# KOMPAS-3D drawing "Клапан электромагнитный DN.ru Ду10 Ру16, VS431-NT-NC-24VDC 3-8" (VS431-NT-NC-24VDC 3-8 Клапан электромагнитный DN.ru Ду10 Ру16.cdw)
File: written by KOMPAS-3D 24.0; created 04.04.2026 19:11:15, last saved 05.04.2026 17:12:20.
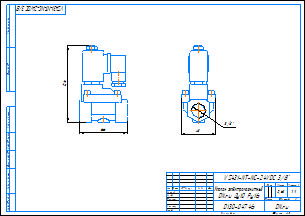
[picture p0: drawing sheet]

Document properties: c3d_UniqueCompID: ef56311e-7521-43dc-8291-0e6108b3d81d; Обозначение: VS400-ET-NC-220VAC 3-8; Наименование: Клапан электромагнитный DN.ru Ду10 Ру16; Автор: artio; Класс точности: c; Знак неуказанной шероховатости: Шероховатость не задана; Рассекать на разрезах: Да; Автор: artio; Форматы листов документа: A3; Полное имя файла: VS431-NT-NC-24VDC 3-8 Клапан электромагнитный DN.ru Ду10 Ру16.m3d; Масса: 0.62; Наименование: Клапан электромагнитный DN.ru Ду10 Ру16; Количество листов документа: 1; Примечание: D130-04746

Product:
- Body: Тело 1  | qty 1
    Масса: 1.030062
- Part/product: Клапан электромагнитный DN.ru Ду10 Ру16  | designation VS431-NT-NC-24VDC 3-8
    Масса: 0.62
    Раздел спецификации: Прочие изделия
    Примечание: D130-04746
    additional columns: ef56311e-7521-43dc-8291-0e6108b3d81d; VS400-ET-NC-220VAC 3-8; artio; c; Шероховатость не задана; Да

Views: Вид 1, Спереди, Проекционный вид 2
Referenced files in C:\Users\artio\OneDrive\Рабочий стол\Клапан электромагнитный DN.ru\VS400-ET-NC\VS400-ET-NC-24VDC\: VS400-ET-NC-24VDC 3-8 Клапан электромагнитный DN.ru Ду10 Ру16.m3d
Referenced files in C:\Users\artio\OneDrive\Рабочий стол\Клапан электромагнитный DN.ru\VS431\VS431-NT-NC\VS431-NT-NC-24VDC\Ду10\: VS431-NT-NC-24VDC 3-8 Клапан электромагнитный DN.ru Ду10 Ру16.m3d
Referenced files in C:\Users\artio\OneDrive\Рабочий стол\Клапан электромагнитный DN.ru\VS400-NT-NC\VS400-NT-NC-24VDC\: VS400-NT-NC-24VDC 3-8 Клапан электромагнитный DN.ru Ду10 Ру16.cdw
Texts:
  VS431-NT-NC-24VDC 3-8
  Клапан электромагнитный
  DN.ru Ду10 Ру16
  VS431-NT-NC-24VDC 3/8"
  VS431-NT-NC-24VDC 3/8"-
  Клапан электромагнитный DN.ru Ду10 Ру16
  VS431-NT-NC-24VDC 3-8 Клапан электромагнитный DN.ru Ду10 Ру16
Dimensions and other numbers on the sheet: 0; 3; 2; 4; 48; 3/8"; 66; 106; 1:1; 1; 0,62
